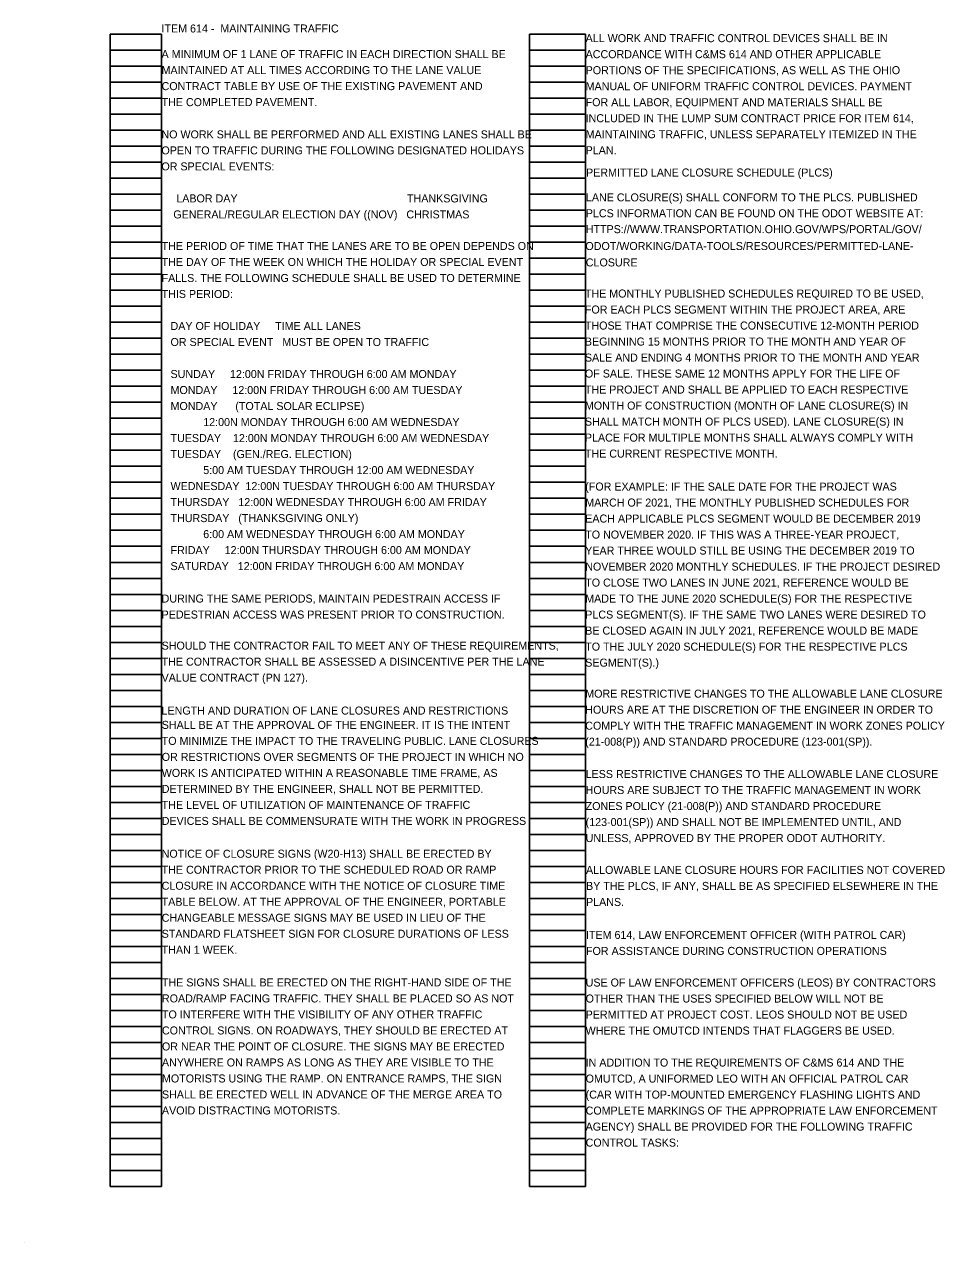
# Model space of a CAD drawing. Extents: x -21.1 to 72.2, y 0 to 46.6.
# Drawn here: x 38.96 to 55.06, y 25.28 to 46.59 of the extents above; entities that cross this region are included whole.
import ezdxf

# ---------------------------------------------------------------- set-up
doc = ezdxf.new("R2010")
doc.units = 0
for name, color, linetype in [('Default', 7, 'Continuous'), ('SH_Data', 7, 'Continuous'), ('SH_Text', 7, 'Continuous')]:
    doc.layers.add(name, color=color, linetype=linetype)

msp = doc.modelspace()

# ---------------------------------------------------------------- linework, layer by layer
at = {"layer": 'SH_Data'}
for p, q in [((40.462, 26.261), (40.462, 46.421)), ((40.462, 46.421), (41.362, 46.421)), ((41.362, 26.261), (41.362, 46.421)), ((47.802, 26.261), (47.802, 46.421)), ((47.802, 46.421), (48.782, 46.421)), ((48.782, 26.261), (48.782, 46.421)), ((40.462, 46.141), (41.362, 46.141)), ((47.802, 46.141), (48.782, 46.141)), ((40.462, 45.861), (41.362, 45.861)), ((47.802, 45.861), (48.782, 45.861)), ((40.462, 45.581), (41.362, 45.581)), ((47.802, 45.581), (48.782, 45.581)), ((40.462, 45.301), (41.362, 45.301)), ((47.802, 45.301), (48.782, 45.301)), ((40.462, 45.021), (41.362, 45.021)), ((47.802, 45.021), (48.782, 45.021)), ((40.462, 44.741), (41.362, 44.741)), ((47.802, 44.741), (48.782, 44.741)), ((40.462, 44.461), (41.362, 44.461)), ((47.802, 44.461), (48.782, 44.461)), ((40.462, 44.181), (41.362, 44.181)), ((47.802, 44.181), (48.782, 44.181)), ((40.462, 43.901), (41.362, 43.901)), ((47.802, 43.901), (48.782, 43.901)), ((40.462, 43.621), (41.362, 43.621)), ((47.802, 43.621), (48.782, 43.621)), ((40.462, 43.341), (41.362, 43.341)), ((47.802, 43.341), (48.782, 43.341)), ((40.462, 43.061), (41.362, 43.061)), ((47.802, 43.061), (48.782, 43.061)), ((40.462, 42.781), (41.362, 42.781)), ((47.802, 42.781), (48.782, 42.781)), ((40.462, 42.501), (41.362, 42.501)), ((47.802, 42.501), (48.782, 42.501)), ((40.462, 42.221), (41.362, 42.221)), ((47.802, 42.221), (48.782, 42.221)), ((40.462, 41.941), (41.362, 41.941)), ((47.802, 41.941), (48.782, 41.941)), ((40.462, 41.661), (41.362, 41.661)), ((47.802, 41.661), (48.782, 41.661)), ((40.462, 41.381), (41.362, 41.381)), ((47.802, 41.381), (48.782, 41.381)), ((40.462, 41.101), (41.362, 41.101)), ((47.802, 41.101), (48.782, 41.101)), ((40.462, 40.821), (41.362, 40.821)), ((47.802, 40.821), (48.782, 40.821)), ((40.462, 40.541), (41.362, 40.541)), ((47.802, 40.541), (48.782, 40.541)), ((40.462, 40.261), (41.362, 40.261)), ((47.802, 40.261), (48.782, 40.261)), ((40.462, 39.981), (41.362, 39.981)), ((47.802, 39.981), (48.782, 39.981)), ((40.462, 39.701), (41.362, 39.701)), ((47.802, 39.701), (48.782, 39.701)), ((40.462, 39.421), (41.362, 39.421)), ((47.802, 39.421), (48.782, 39.421)), ((40.462, 39.141), (41.362, 39.141)), ((47.802, 39.141), (48.782, 39.141)), ((40.462, 38.861), (41.362, 38.861)), ((47.802, 38.861), (48.782, 38.861)), ((40.462, 38.581), (41.362, 38.581)), ((47.802, 38.581), (48.782, 38.581)), ((40.462, 38.301), (41.362, 38.301)), ((47.802, 38.301), (48.782, 38.301)), ((40.462, 38.021), (41.362, 38.021)), ((47.802, 38.021), (48.782, 38.021)), ((40.462, 37.741), (41.362, 37.741)), ((47.802, 37.741), (48.782, 37.741)), ((40.462, 37.461), (41.362, 37.461)), ((47.802, 37.461), (48.782, 37.461)), ((40.462, 37.181), (41.362, 37.181)), ((47.802, 37.181), (48.782, 37.181)), ((40.462, 36.901), (41.362, 36.901)), ((47.802, 36.901), (48.782, 36.901)), ((40.462, 36.621), (41.362, 36.621)), ((47.802, 36.621), (48.782, 36.621)), ((40.462, 36.341), (41.362, 36.341)), ((47.802, 36.341), (48.782, 36.341)), ((40.462, 36.061), (41.362, 36.061)), ((47.802, 36.061), (48.782, 36.061)), ((40.462, 35.781), (41.362, 35.781)), ((47.802, 35.781), (48.782, 35.781)), ((40.462, 35.501), (41.362, 35.501)), ((47.802, 35.501), (48.782, 35.501)), ((40.462, 35.221), (41.362, 35.221)), ((47.802, 35.221), (48.782, 35.221)), ((40.462, 34.941), (41.362, 34.941)), ((47.802, 34.941), (48.782, 34.941)), ((40.462, 34.661), (41.362, 34.661)), ((47.802, 34.661), (48.782, 34.661)), ((40.462, 34.381), (41.362, 34.381)), ((47.802, 34.381), (48.782, 34.381)), ((40.462, 34.101), (41.362, 34.101)), ((47.802, 34.101), (48.782, 34.101)), ((40.462, 33.821), (41.362, 33.821)), ((47.802, 33.821), (48.782, 33.821)), ((40.462, 33.541), (41.362, 33.541)), ((47.802, 33.541), (48.782, 33.541)), ((40.462, 33.261), (41.362, 33.261)), ((47.802, 33.261), (48.782, 33.261)), ((40.462, 32.981), (41.362, 32.981)), ((47.802, 32.981), (48.782, 32.981)), ((40.462, 32.701), (41.362, 32.701)), ((47.802, 32.701), (48.782, 32.701)), ((40.462, 32.421), (41.362, 32.421)), ((47.802, 32.421), (48.782, 32.421)), ((40.462, 32.141), (41.362, 32.141)), ((47.802, 32.141), (48.782, 32.141)), ((40.462, 31.861), (41.362, 31.861)), ((47.802, 31.861), (48.782, 31.861)), ((40.462, 31.581), (41.362, 31.581)), ((47.802, 31.581), (48.782, 31.581)), ((40.462, 31.301), (41.362, 31.301)), ((47.802, 31.301), (48.782, 31.301)), ((40.462, 31.021), (41.362, 31.021)), ((47.802, 31.021), (48.782, 31.021)), ((40.462, 30.741), (41.362, 30.741)), ((47.802, 30.741), (48.782, 30.741)), ((40.462, 30.461), (41.362, 30.461)), ((47.802, 30.461), (48.782, 30.461)), ((40.462, 30.181), (41.362, 30.181)), ((47.802, 30.181), (48.782, 30.181)), ((40.462, 29.901), (41.362, 29.901)), ((47.802, 29.901), (48.782, 29.901)), ((40.462, 29.621), (41.362, 29.621)), ((47.802, 29.621), (48.782, 29.621)), ((40.462, 29.341), (41.362, 29.341)), ((47.802, 29.341), (48.782, 29.341)), ((40.462, 29.061), (41.362, 29.061)), ((47.802, 29.061), (48.782, 29.061)), ((40.462, 28.781), (41.362, 28.781)), ((47.802, 28.781), (48.782, 28.781)), ((40.462, 28.501), (41.362, 28.501)), ((47.802, 28.501), (48.782, 28.501)), ((40.462, 28.221), (41.362, 28.221)), ((47.802, 28.221), (48.782, 28.221)), ((40.462, 27.941), (41.362, 27.941)), ((47.802, 27.941), (48.782, 27.941)), ((40.462, 27.661), (41.362, 27.661)), ((47.802, 27.661), (48.782, 27.661)), ((40.462, 27.381), (41.362, 27.381)), ((47.802, 27.381), (48.782, 27.381)), ((40.462, 27.101), (41.362, 27.101)), ((47.802, 27.101), (48.782, 27.101)), ((40.462, 26.821), (41.362, 26.821)), ((47.802, 26.821), (48.782, 26.821)), ((40.462, 26.541), (41.362, 26.541)), ((47.802, 26.541), (48.782, 26.541)), ((40.462, 26.261), (41.362, 26.261)), ((47.802, 26.261), (48.782, 26.261)), ((38.962, 25.281), (38.962, 25.281))]:
    msp.add_line(p, q, dxfattribs=at)

# ---------------------------------------------------------------- texts
at = {"layer": 'Default'}
for s, p in [('PERMITTED LANE CLOSURE SCHEDULE (PLCS)', (48.789, 43.93)), ('PLCS INFORMATION CAN BE FOUND ON THE ODOT WEBSITE AT:', (48.785, 43.217)), ('HTTPS://WWW.TRANSPORTATION.OHIO.GOV/WPS/PORTAL/GOV/', (48.784, 42.939)), ('ODOT/WORKING/DATA-TOOLS/RESOURCES/PERMITTED-LANE-', (48.778, 42.644)), ('CLOSURE', (48.785, 42.357)), ('THE MONTHLY PUBLISHED SCHEDULES REQUIRED TO BE USED,', (48.769, 41.813)), ('FOR EACH PLCS SEGMENT WITHIN THE PROJECT AREA, ARE', (48.769, 41.533)), ('THOSE THAT COMPRISE THE CONSECUTIVE 12-MONTH PERIOD', (48.769, 41.253)), ('BEGINNING 15 MONTHS PRIOR TO THE MONTH AND YEAR OF', (48.769, 40.973)), ('SALE AND ENDING 4 MONTHS PRIOR TO THE MONTH AND YEAR', (48.769, 40.693)), ('OF SALE. THESE SAME 12 MONTHS APPLY FOR THE LIFE OF', (48.769, 40.413)), ('THE PROJECT AND SHALL BE APPLIED TO EACH RESPECTIVE', (48.769, 40.133)), ('MONTH OF CONSTRUCTION (MONTH OF LANE CLOSURE(S) IN', (48.769, 39.853)), ('SHALL MATCH MONTH OF PLCS USED). LANE CLOSURE(S) IN', (48.769, 39.573)), ('PLACE FOR MULTIPLE MONTHS SHALL ALWAYS COMPLY WITH ', (48.769, 39.293)), ('THE CURRENT RESPECTIVE MONTH.', (48.769, 39.013)), ('(FOR EXAMPLE: IF THE SALE DATE FOR THE PROJECT WAS', (48.775, 38.437)), ('MARCH OF 2021, THE MONTHLY PUBLISHED SCHEDULES FOR', (48.775, 38.157)), ('EACH APPLICABLE PLCS SEGMENT WOULD BE DECEMBER 2019', (48.775, 37.877)), ('TO NOVEMBER 2020. IF THIS WAS A THREE-YEAR PROJECT,', (48.775, 37.597)), ('YEAR THREE WOULD STILL BE USING THE DECEMBER 2019 TO', (48.775, 37.317)), ('NOVEMBER 2020 MONTHLY SCHEDULES. IF THE PROJECT DESIRED', (48.775, 37.037)), ('TO CLOSE TWO LANES IN JUNE 2021, REFERENCE WOULD BE', (48.775, 36.757)), ('MADE TO THE JUNE 2020 SCHEDULE(S) FOR THE RESPECTIVE', (48.775, 36.477)), ('PLCS SEGMENT(S). IF THE SAME TWO LANES WERE DESIRED TO', (48.775, 36.197)), ('BE CLOSED AGAIN IN JULY 2021, REFERENCE WOULD BE MADE', (48.775, 35.917)), ('TO THE JULY 2020 SCHEDULE(S) FOR THE RESPECTIVE PLCS', (48.775, 35.637)), ('SEGMENT(S).)', (48.775, 35.357)), ('MORE RESTRICTIVE CHANGES TO THE ALLOWABLE LANE CLOSURE', (48.775, 34.814)), ('HOURS ARE AT THE DISCRETION OF THE ENGINEER IN ORDER TO', (48.775, 34.534)), ('COMPLY WITH THE TRAFFIC MANAGEMENT IN WORK ZONES POLICY', (48.775, 34.254)), ('(21-008(P)) AND STANDARD PROCEDURE (123-001(SP)).', (48.775, 33.974)), ('LESS RESTRICTIVE CHANGES TO THE ALLOWABLE LANE CLOSURE', (48.782, 33.408)), ('HOURS ARE SUBJECT TO THE TRAFFIC MANAGEMENT IN WORK', (48.782, 33.128)), ('ZONES POLICY (21-008(P)) AND STANDARD PROCEDURE', (48.782, 32.848)), ('(123-001(SP)) AND SHALL NOT BE IMPLEMENTED UNTIL, AND', (48.782, 32.568)), ('UNLESS, APPROVED BY THE PROPER ODOT AUTHORITY.', (48.782, 32.288)), ('ALLOWABLE LANE CLOSURE HOURS FOR FACILITIES NOT COVERED', (48.789, 31.731)), ('BY THE PLCS, IF ANY, SHALL BE AS SPECIFIED ELSEWHERE IN THE', (48.789, 31.451)), ('PLANS.', (48.789, 31.171))]:
    msp.add_text(s, height=0.14, dxfattribs=at).set_placement(p)
at = {"layer": 'SH_Text'}
for s, p in [('ITEM 614 -  MAINTAINING TRAFFIC', (41.361, 46.449)), ('ALL WORK AND TRAFFIC CONTROL DEVICES SHALL BE IN', (48.782, 46.28)), ('A MINIMUM OF 1 LANE OF TRAFFIC IN EACH DIRECTION SHALL BE', (41.362, 46.001)), ('ACCORDANCE WITH C&MS 614 AND OTHER APPLICABLE', (48.782, 46)), ('MAINTAINED AT ALL TIMES ACCORDING TO THE LANE VALUE ', (41.362, 45.721)), ('PORTIONS OF THE SPECIFICATIONS, AS WELL AS THE OHIO', (48.782, 45.72)), ('CONTRACT TABLE BY USE OF THE EXISTING PAVEMENT AND', (41.362, 45.441)), ('MANUAL OF UNIFORM TRAFFIC CONTROL DEVICES. PAYMENT', (48.782, 45.44)), ('THE COMPLETED PAVEMENT.', (41.362, 45.161)), ('FOR ALL LABOR, EQUIPMENT AND MATERIALS SHALL BE', (48.782, 45.16)), ('INCLUDED IN THE LUMP SUM CONTRACT PRICE FOR ITEM 614,', (48.782, 44.88)), ('NO WORK SHALL BE PERFORMED AND ALL EXISTING LANES SHALL BE', (41.36, 44.597)), ('MAINTAINING TRAFFIC, UNLESS SEPARATELY ITEMIZED IN THE', (48.782, 44.6)), ('OPEN TO TRAFFIC DURING THE FOLLOWING DESIGNATED HOLIDAYS', (41.36, 44.317)), ('PLAN.', (48.782, 44.32)), ('OR SPECIAL EVENTS:', (41.36, 44.037)), ('     LABOR DAY                                                         THANKSGIVING', (41.36, 43.477)), ('LANE CLOSURE(S) SHALL CONFORM TO THE PLCS. PUBLISHED', (48.787, 43.495)), ('    GENERAL/REGULAR ELECTION DAY ((NOV)   CHRISTMAS', (41.36, 43.197)), ('THE PERIOD OF TIME THAT THE LANES ARE TO BE OPEN DEPENDS ON', (41.363, 42.645)), ('THE DAY OF THE WEEK ON WHICH THE HOLIDAY OR SPECIAL EVENT', (41.363, 42.365)), ('FALLS. THE FOLLOWING SCHEDULE SHALL BE USED TO DETERMINE', (41.363, 42.085)), ('THIS PERIOD:', (41.363, 41.805)), ('   DAY OF HOLIDAY     TIME ALL LANES', (41.363, 41.245)), ('   OR SPECIAL EVENT   MUST BE OPEN TO TRAFFIC', (41.363, 40.965)), ('   SUNDAY     12:00N FRIDAY THROUGH 6:00 AM MONDAY', (41.363, 40.405)), ('   MONDAY     12:00N FRIDAY THROUGH 6:00 AM TUESDAY', (41.363, 40.125)), ('   MONDAY      (TOTAL SOLAR ECLIPSE)', (41.363, 39.845)), ('              12:00N MONDAY THROUGH 6:00 AM WEDNESDAY', (41.363, 39.565)), ('   TUESDAY    12:00N MONDAY THROUGH 6:00 AM WEDNESDAY', (41.363, 39.285)), ('   TUESDAY    (GEN./REG. ELECTION)', (41.363, 39.005)), ('              5:00 AM TUESDAY THROUGH 12:00 AM WEDNESDAY', (41.363, 38.725)), ('   WEDNESDAY  12:00N TUESDAY THROUGH 6:00 AM THURSDAY', (41.363, 38.445)), ('   THURSDAY   12:00N WEDNESDAY THROUGH 6:00 AM FRIDAY', (41.363, 38.165)), ('   THURSDAY   (THANKSGIVING ONLY)', (41.363, 37.885)), ('              6:00 AM WEDNESDAY THROUGH 6:00 AM MONDAY', (41.363, 37.605)), ('   FRIDAY     12:00N THURSDAY THROUGH 6:00 AM MONDAY', (41.363, 37.325)), ('   SATURDAY   12:00N FRIDAY THROUGH 6:00 AM MONDAY', (41.363, 37.045)), ('DURING THE SAME PERIODS, MAINTAIN PEDESTRAIN ACCESS IF', (41.363, 36.478)), ('PEDESTRIAN ACCESS WAS PRESENT PRIOR TO CONSTRUCTION.', (41.363, 36.198)), ('SHOULD THE CONTRACTOR FAIL TO MEET ANY OF THESE REQUIREMENTS,', (41.363, 35.654)), ('THE CONTRACTOR SHALL BE ASSESSED A DISINCENTIVE PER THE LANE', (41.363, 35.374)), ('VALUE CONTRACT (PN 127).', (41.363, 35.094)), ('LENGTH AND DURATION OF LANE CLOSURES AND RESTRICTIONS', (41.362, 34.518)), ('SHALL BE AT THE APPROVAL OF THE ENGINEER. IT IS THE INTENT', (41.365, 34.268)), ('TO MINIMIZE THE IMPACT TO THE TRAVELING PUBLIC. LANE CLOSURES', (41.365, 33.988)), ('OR RESTRICTIONS OVER SEGMENTS OF THE PROJECT IN WHICH NO', (41.365, 33.708)), ('WORK IS ANTICIPATED WITHIN A REASONABLE TIME FRAME, AS', (41.365, 33.428)), ('DETERMINED BY THE ENGINEER, SHALL NOT BE PERMITTED.', (41.365, 33.148)), ('THE LEVEL OF UTILIZATION OF MAINTENANCE OF TRAFFIC', (41.365, 32.868)), ('DEVICES SHALL BE COMMENSURATE WITH THE WORK IN PROGRESS', (41.365, 32.588)), ('NOTICE OF CLOSURE SIGNS (W20-H13) SHALL BE ERECTED BY', (41.364, 32.014)), ('THE CONTRACTOR PRIOR TO THE SCHEDULED ROAD OR RAMP', (41.364, 31.734)), ('CLOSURE IN ACCORDANCE WITH THE NOTICE OF CLOSURE TIME', (41.364, 31.454)), ('TABLE BELOW. AT THE APPROVAL OF THE ENGINEER, PORTABLE', (41.364, 31.174)), ('CHANGEABLE MESSAGE SIGNS MAY BE USED IN LIEU OF THE', (41.364, 30.894)), ('STANDARD FLATSHEET SIGN FOR CLOSURE DURATIONS OF LESS', (41.364, 30.614)), ('ITEM 614, LAW ENFORCEMENT OFFICER (WITH PATROL CAR)', (48.788, 30.594)), ('THAN 1 WEEK.', (41.364, 30.334)), ('FOR ASSISTANCE DURING CONSTRUCTION OPERATIONS', (48.788, 30.314)), ('THE SIGNS SHALL BE ERECTED ON THE RIGHT-HAND SIDE OF THE', (41.369, 29.763)), ('USE OF LAW ENFORCEMENT OFFICERS (LEOS) BY CONTRACTORS', (48.782, 29.761)), ('ROAD/RAMP FACING TRAFFIC. THEY SHALL BE PLACED SO AS NOT', (41.369, 29.483)), ('OTHER THAN THE USES SPECIFIED BELOW WILL NOT BE', (48.782, 29.481)), ('TO INTERFERE WITH THE VISIBILITY OF ANY OTHER TRAFFIC', (41.369, 29.203)), ('PERMITTED AT PROJECT COST. LEOS SHOULD NOT BE USED', (48.782, 29.201)), ('CONTROL SIGNS. ON ROADWAYS, THEY SHOULD BE ERECTED AT', (41.369, 28.923)), ('WHERE THE OMUTCD INTENDS THAT FLAGGERS BE USED.', (48.782, 28.921)), ('OR NEAR THE POINT OF CLOSURE. THE SIGNS MAY BE ERECTED', (41.369, 28.643)), ('ANYWHERE ON RAMPS AS LONG AS THEY ARE VISIBLE TO THE', (41.369, 28.363)), ('IN ADDITION TO THE REQUIREMENTS OF C&MS 614 AND THE', (48.782, 28.361)), ('MOTORISTS USING THE RAMP. ON ENTRANCE RAMPS, THE SIGN', (41.369, 28.083)), ('OMUTCD, A UNIFORMED LEO WITH AN OFFICIAL PATROL CAR', (48.782, 28.081)), ('SHALL BE ERECTED WELL IN ADVANCE OF THE MERGE AREA TO', (41.369, 27.803)), ('(CAR WITH TOP-MOUNTED EMERGENCY FLASHING LIGHTS AND', (48.782, 27.801)), ('AVOID DISTRACTING MOTORISTS.', (41.369, 27.523)), ('COMPLETE MARKINGS OF THE APPROPRIATE LAW ENFORCEMENT', (48.782, 27.521)), ('AGENCY) SHALL BE PROVIDED FOR THE FOLLOWING TRAFFIC', (48.782, 27.241)), ('CONTROL TASKS:', (48.782, 26.961))]:
    msp.add_text(s, height=0.14, dxfattribs=at).set_placement(p)

doc.saveas('drawing.dxf')
